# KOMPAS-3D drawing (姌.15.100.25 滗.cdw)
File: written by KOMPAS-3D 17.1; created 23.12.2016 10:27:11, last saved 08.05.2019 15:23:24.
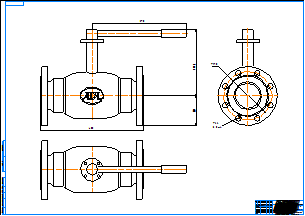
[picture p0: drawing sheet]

Sheet 1: A0, landscape

Title block, sheet 1: name: КШ.15.100.25 фф; material: Внимание! Данный продукт является объектом авторского права ООО «Торговый Дом АДЛ». / Запрещается изменение, копирование, распространение / (в том числе путем копирования на другие сайты и ресурсы в Интернете) / или любое иное использование информации и объектов без предварительного / согласия правообладателя (ООО «Торговый Дом АДЛ»).; sheets: 1; organisation: ООО "Торговый дом АДЛ"; sheet format: A0; stored path: C:\Users\tra\Desktop\2д чертежи\Шаровые краны БИВАЛ\КШ_Бивал_серия_14_15\KOMPAS_2D\КШ.15.100.25 фф.cdw

Views: Вид 1, Проекционный вид 2, Проекционный вид 3
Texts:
  Klimkovich
  ADL
Dimensions and other numbers on the sheet: 400; 370; 258,4; 115; 190; 22; 8 Отв.; 1:1; 1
